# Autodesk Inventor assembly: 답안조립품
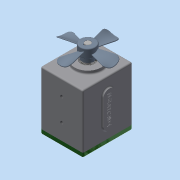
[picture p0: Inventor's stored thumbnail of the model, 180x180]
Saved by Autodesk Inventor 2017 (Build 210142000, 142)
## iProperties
Part Number: 답안조립품
Material: 일반
Document SubType Name: Assembly
Designer: MRC
Mass: 2669.46 g
Surface Area: 1952.92 cm^2
Volume: 798.897 cm^3
Density: 3.34143 g/cm^3
Author: MRC
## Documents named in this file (17)
- C:\Users\MRC\Desktop\610205V1009\답안조립품.iam
- C:\Users\MRC\Desktop\610205V1009\본체.ipt
- C:\Users\MRC\Desktop\610205V1009\가변스프링.ipt
- C:\Users\MRC\Desktop\610205V1009\멈춤나사 M3x8.ipt
- C:\Users\MRC\Desktop\610205V1009\메인 기어 축.ipt
- C:\Users\MRC\Desktop\610205V1009\베어링 608.ipt
- C:\Users\MRC\Desktop\610205V1009\베어링 6903.ipt
- C:\Users\MRC\Desktop\610205V1009\볼트 M4 x 10.ipt
- C:\Users\MRC\Desktop\610205V1009\부시.ipt
- C:\Users\MRC\Desktop\610205V1009\서브 기어 축.ipt
- C:\Users\MRC\Desktop\610205V1009\슬라이더.ipt
- C:\Users\MRC\Desktop\610205V1009\오일 실 8 22 7.ipt
- C:\Users\MRC\Desktop\610205V1009\오일 실 17 30 8.ipt
- C:\Users\MRC\Desktop\610205V1009\커버.ipt
- C:\Users\MRC\Desktop\610205V1009\키 5 x 5 x 24.ipt
- C:\Users\MRC\Desktop\610205V1009\팬날개.ipt
- 팬날개.ipt
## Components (1 placed, 1 different names)
1. 가변스프링:1
